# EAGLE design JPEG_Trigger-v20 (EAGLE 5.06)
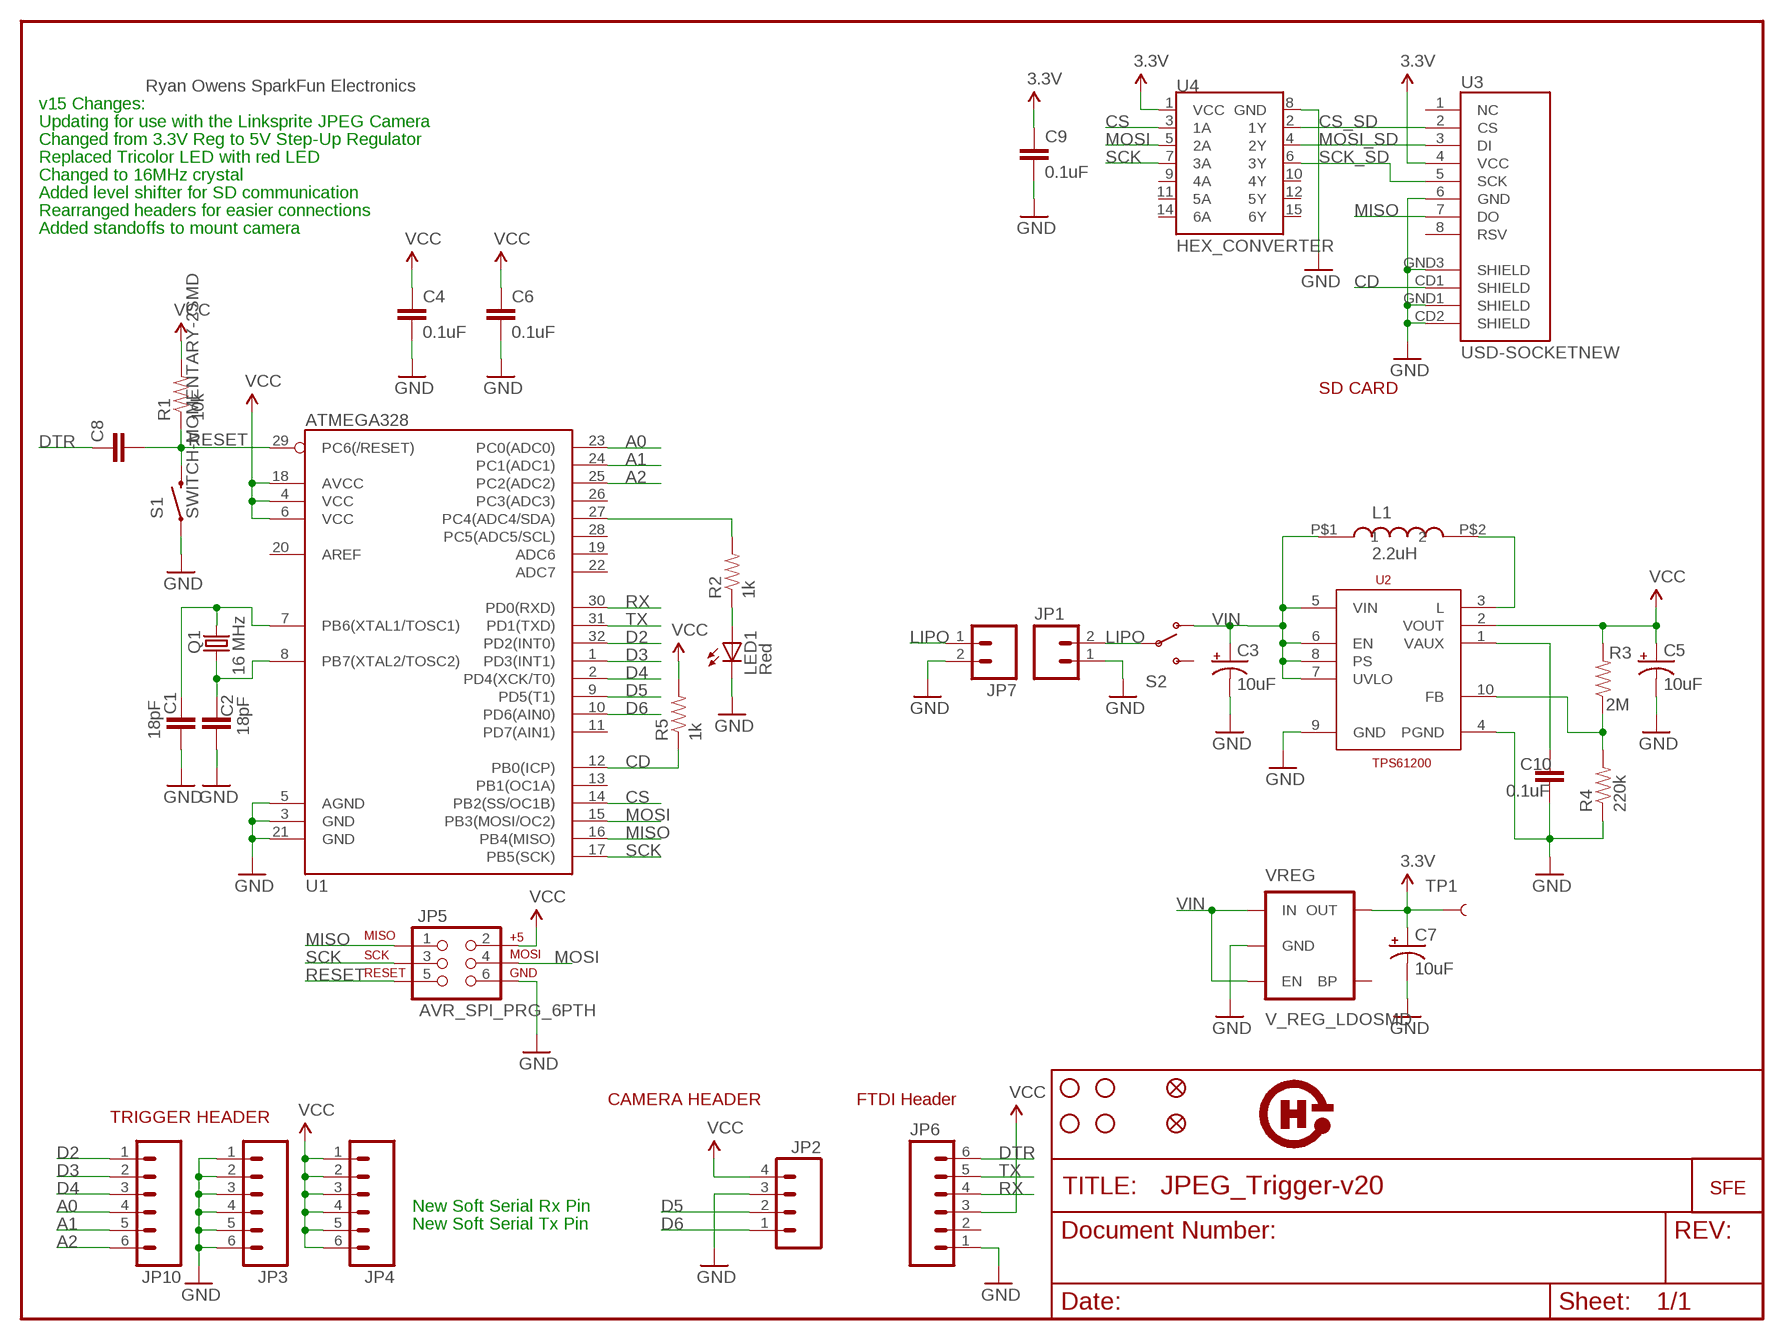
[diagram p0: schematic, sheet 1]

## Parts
C1  18pF  CAP0402-CAP  [0402-CAP]
C2  18pF  CAP0402-CAP  [0402-CAP]
C3  10uF  CAP_POL1206  [EIA3216]
C4  0.1uF  CAP0402-CAP  [0402-CAP]
C5  10uF  CAP_POL1206  [EIA3216]
C6  0.1uF  CAP0402-CAP  [0402-CAP]
C7  10uF  CAP_POL1206  [EIA3216]
C8  .1uF  CAP0402-CAP  [0402-CAP]
C9  0.1uF  CAP0402-CAP  [0402-CAP]
C10  0.1uF  CAP0402-CAP  [0402-CAP]
JP1  M02-JST-2MM-SMT  [JST-2-SMD]
JP2  M04PTH  [1X04]
JP3  M06SIP  [1X06]
JP4  M06SIP  [1X06]
JP5  AVR_SPI_PRG_6PTH  [2X3]
JP6  M06SIP  [1X06]
JP7  M02PTH  [1X02]
JP8  STAND-OFF  [STAND-OFF]
JP9  STAND-OFF  [STAND-OFF]
JP10  M06SIP  [1X06]
JP11  STAND-OFF  [STAND-OFF]
JP12  STAND-OFF  [STAND-OFF]
JP13  FIDUCIAL1X2  [FIDUCIAL-1X2]
JP14  FIDUCIAL1X2  [FIDUCIAL-1X2]
L1  2.2uH  VLF4012A  [VLF4012A]
LED1  Red  LED0603  [LED-0603]
Q1  16 MHz  CRYSTAL5X3  [CRYSTAL-SMD-5X3]
R1  10k  RESISTOR0402-RES  [0402-RES]
R2  1k  RESISTOR0402-RES  [0402-RES]
R3  2M  RESISTOR0402-RES  [0402-RES]
R4  220k  RESISTOR0402-RES  [0402-RES]
R5  1k  RESISTOR0402-RES  [0402-RES]
S1  SWITCH-MOMENTARY-2SMD  [TACTILE_SWITCH_SMD]
S2  SWITCH-SPSTSMD2  [SWITCH-SPDT-SMD]
TP1  TEST-POINT3X5  [PAD.03X.05]
U1  ATMEGA328  ATMEGA168  [TQFP32-08]
U2  TPS61200  [DRC-S-PVSON-N10]
U3  USD-SOCKETNEW  [MICRO-SD-SOCKET-PP]
U4  HEX_CONVERTER  [SO016]
U$1  LOGO-SFENEW  [SFE-NEW-WEBLOGO]
U$2  OSHW-LOGO  [OSHW-LOGO]
VREG  V_REG_LDOSMD  [SOT23-5]

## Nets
3.3V: C7.A(+) C9.1 TP1.P$1 U3.4(VCC) U4.1(VCC) VREG.5(OUT)
A0: JP10.4 U1.23(PC0(ADC0))
A1: JP10.5 U1.24(PC1(ADC1))
A2: JP10.6 U1.25(PC2(ADC2))
CD: R5.1 U1.12(PB0(ICP)) U3.CD1(SHIELD)
CS: U1.14(PB2(SS/OC1B)) U4.3(1A)
CS_SD: U3.2(CS) U4.2(1Y)
D2: JP10.1 U1.32(PD2(INT0))
D3: JP10.2 U1.1(PD3(INT1))
D4: JP10.3 U1.2(PD4(XCK/T0))
D5: JP2.2 U1.9(PD5(T1))
D6: JP2.1 U1.10(PD6(AIN0))
DTR: C8.1 JP6.6
GND: C1.2 C2.2 C3.C(-) C4.2 C5.C(-) C6.2 C7.C(-) C9.2 C10.2 JP1.1 JP2.3 JP3.1 JP3.2 JP3.3 JP3.4 JP3.5 JP3.6 JP5.6 JP6.1 JP7.2 LED1.C R4.1 S1.1 U1.3(GND) U1.5(AGND) U1.21(GND) U2.4(PGND) U2.9(GND) U3.6(GND) U3.CD2(SHIELD) U3.GND1(SHIELD) U3.GND3(SHIELD) U4.8(GND) VREG.2(GND)
LIPO: JP1.2 JP7.1 S2.2(P)
MISO: JP5.1 U1.16(PB4(MISO)) U3.7(DO)
MOSI: JP5.4 U1.15(PB3(MOSI/OC2)) U4.5(2A)
MOSI_SD: U3.3(DI) U4.4(2Y)
N$1: C1.1 Q1.3 U1.7(PB6(XTAL1/TOSC1))
N$2: C2.1 Q1.1 U1.8(PB7(XTAL2/TOSC2))
N$4: LED1.A R2.1
N$5: L1.P$2 U2.3(L)
N$6: C10.1 U2.1(VAUX)
N$7: R3.1 R4.2 U2.10(FB)
R: R2.2 U1.27(PC4(ADC4/SDA))
RESET: C8.2 JP5.5 R1.1 S1.3 U1.29(PC6(/RESET))
RX: JP6.4 U1.30(PD0(RXD))
SCK: JP5.3 U1.17(PB5(SCK)) U4.7(3A)
SCK_SD: U3.5(SCK) U4.6(3Y)
TX: JP6.5 U1.31(PD1(TXD))
VCC: C4.1 C5.A(+) C6.1 JP2.4 JP4.1 JP4.2 JP4.3 JP4.4 JP4.5 JP4.6 JP5.2 JP6.3 R1.2 R3.2 R5.2 U1.4(VCC) U1.6(VCC) U1.18(AVCC) U2.2(VOUT)
VIN: C3.A(+) L1.P$1 S2.1(O) U2.5(VIN) U2.6(EN) U2.7(UVLO) U2.8(PS) VREG.1(IN) VREG.3(EN)
Unconnected: JP6.2 S2.3(S) U1.11(PD7(AIN1)) U1.13(PB1(OC1A)) U1.19(ADC6) U1.20(AREF) U1.22(ADC7) U1.26(PC3(ADC3)) U1.28(PC5(ADC5/SCL)) U3.1(NC) U3.8(RSV) U4.9(4A) U4.10(4Y) U4.11(5A) U4.12(5Y) U4.14(6A) U4.15(6Y) VREG.4(BP)

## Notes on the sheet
- Ryan Owens SparkFun Electronics
- v15 Changes:
- Updating for use with the Linksprite JPEG Camera
- Changed from 3.3V Reg to 5V Step-Up Regulator
- Replaced Tricolor LED with red LED
- Changed to 16MHz crystal
- Added level shifter for SD communication
- Rearranged headers for easier connections
- Added standoffs to mount camera
- SD CARD
- CAMERA HEADER | FTDI Header
- TRIGGER HEADER
- New Soft Serial Rx Pin
- New Soft Serial Tx Pin

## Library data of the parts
C1 C2 C4 C6 C8-C10 = SparkFun:CAP: Capacitor
C3 C5 C7 = SparkFun:CAP_POL: Capacitor Polarized
JP1 JP7 = SparkFun:M02: Header 2
JP2 = SparkFun:M04: Header 4 Standard 4-pin 0.1" header. Use with straight break away headers (SKU : PRT-00116), right angle break away headers (PRT-00553), swiss pins (PRT-00743), machine pins (PRT-00117), and female headers (PRT-00115). Molex polarized connector foot print use with SKU : PRT-08231 with associated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
JP3 JP4 JP6 JP10 = SparkFun:M06: Header 6 Standard 6-pin 0.1" header. Use with straight break away headers (SKU : PRT-00116), right angle break away headers (PRT-00553), swiss pins (PRT-00743), machine pins (PRT-00117), and female headers (PRT-00115). Molex polarized connector foot print use with SKU : PRT-08094 with associated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
JP5 = SparkFun:AVR_SPI_PRG_6: AVR ISP 6 Pin This is the reduced ISP connector for AVR programming. Common on Arduino. This footprint will take up less PCB space and can be used with a 10-pin to 6-pin adapter such as SKU: BOB-08508
JP8 JP9 JP11 JP12 = SparkFun:STAND-OFF: Stand Off
JP13 JP14 = SparkFun:FIDUCIAL: Fiducial Alignment Points
L1 = PEBBLE:VLF4012A
LED1 = SparkFun:LED: LEDs
Q1 = SparkFun:CRYSTAL: Crystals
R1-R5 = SparkFun:RESISTOR: Resistor
S1 = SparkFun:SWITCH-MOMENTARY-2
S2 = SparkFun:SWITCH-SPST: SPST Switch Simple slide switch. Spark Fun Electronics SKU : COM-00102
TP1 = SparkFun:TEST-POINT
U1 = SparkFun:ATMEGA168
U2 = texas:TPS61200
U3 = SparkFun:USD-SOCKET: microSD Socket Push-push type uSD socket. Schematic element and footprint production proven. Spark Fun Electronics SKU : PRT-00127. tDoc lines correctly indicate media card edge positions when inserting (unlocked, locked, depressed).
U4 = SparkFun:HEX_CONVERTER
U$1 = SparkFun:LOGO-SFE: Spark Fun Electronics PCB Logo
U$2 = OSHW:OSHW-LOGO
VREG = SparkFun:V_REG_LDO: Voltage Regulator LDO Standard 150mA LDO voltage regulator in SOT-23 layout. Micrel part MIC5205. BP (by-pass) pin is used to lower output noise with 470pF cap.

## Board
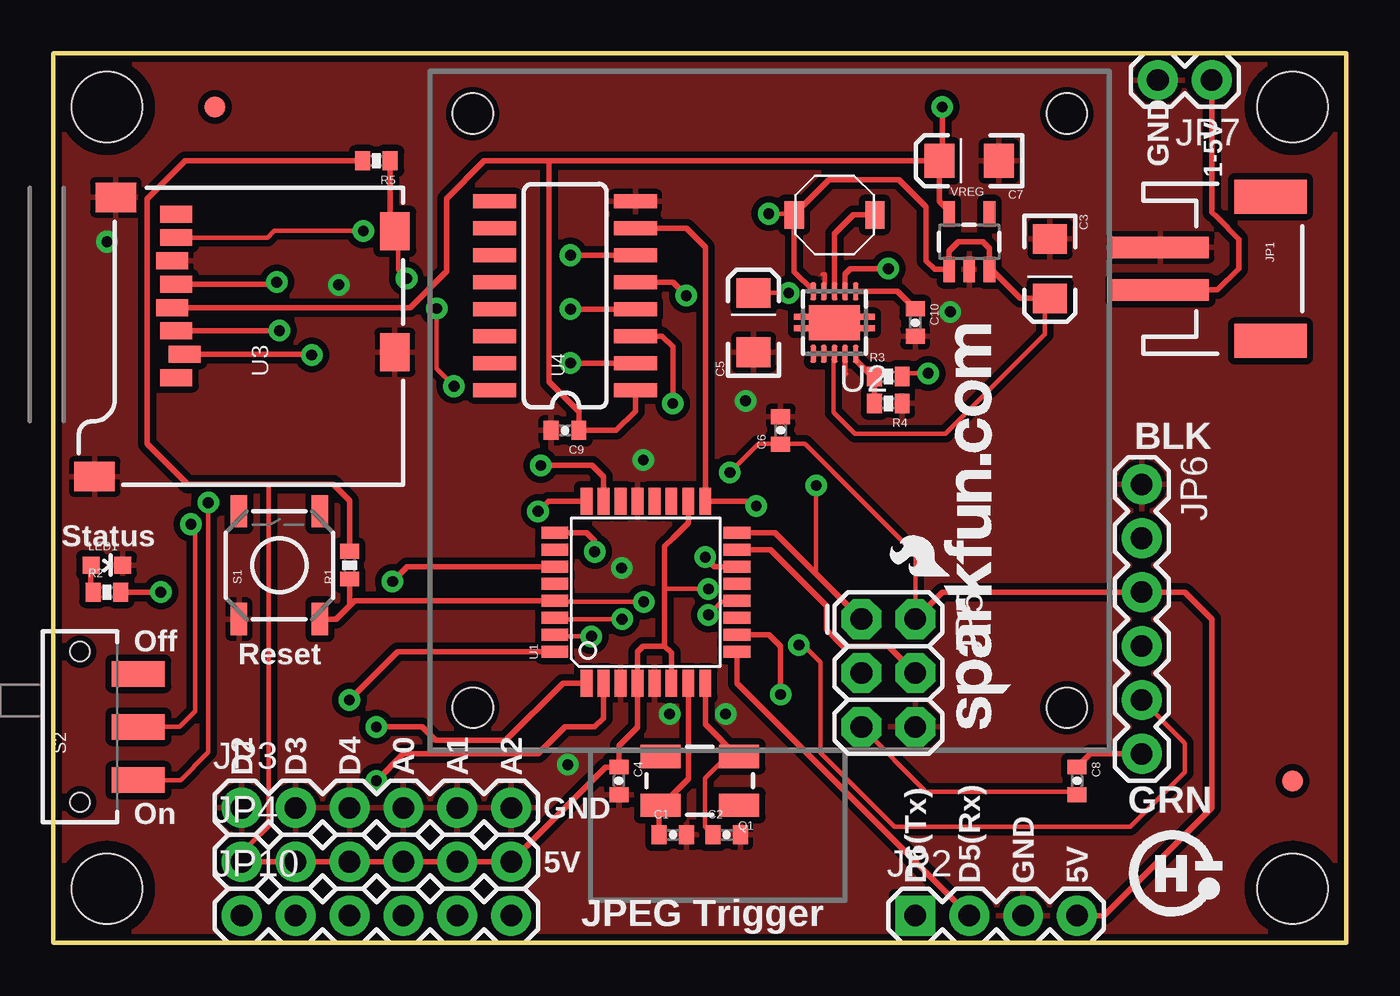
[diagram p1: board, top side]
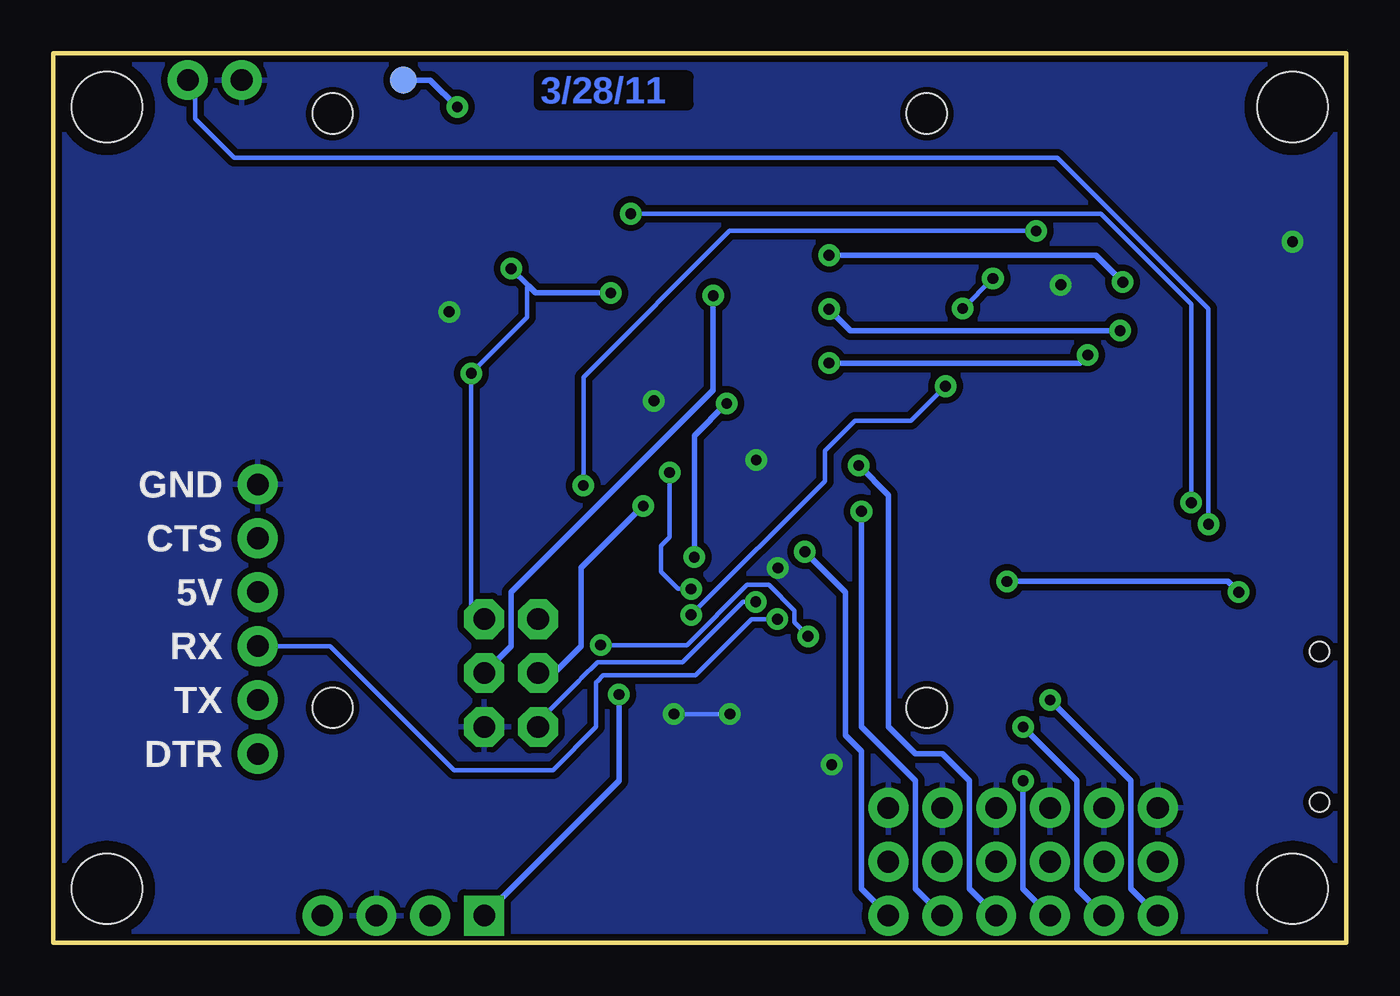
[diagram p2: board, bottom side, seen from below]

Size 60.96 x 41.91 mm. Coordinates in mm from the lower left corner, seen from the top.
Outline: 0,0 60.96,0 60.96,41.91 0,41.91 0,0
Copper layers (1*16): Top 0.035mm / dielectric 1.5mm / Bottom 0.035mm
Design rules "SparkFun": minimum track width 8mil, minimum drill 20mil, track to track 8mil, track to pad 8mil, pad to pad 8mil, via to via 8mil, smd to smd 8mil, copper to edge 9mil, drill to drill 8mil, minimum pad ring 12mil, minimum via ring 10mil, stop-mask expansion 4mil, vias tented up to drill 20mil, thermal gap 10mil
Holes 1.89 mm at 19.78,39.06 47.78,39.06 47.78,11.06 19.78,11.06

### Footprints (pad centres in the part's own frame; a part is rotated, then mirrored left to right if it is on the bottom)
0402-CAP = smd 0.7 x 0.9: 1 -0.65,0; 2 0.65,0
EIA3216 = smd 1.4 x 1.6: A 1.4,0; C -1.4,0
JST-2-SMD = smd 1 x 4.6: 1 -1,-3.7; 2 1,-3.7 | smd 1.6 x 3.4: NC1 -3.4,1.5; NC2 3.4,1.5
1X04 = drill 1.016 pad 1.88 square: 1 0,0 | drill 1.016 pad 1.88 round: 2 2.54,0; 3 5.08,0; 4 7.62,0
1X06 = drill 1.016 pad 1.88 round: 1 0,0; 2 2.54,0; 3 5.08,0; 4 7.62,0; 5 10.16,0; 6 12.7,0
2X3 = drill 1.016 pad 1.88 octagon: 1 0,0; 2 0,2.54; 3 2.54,0; 4 2.54,2.54; 5 5.08,0; 6 5.08,2.54
1X02 = drill 1.016 pad 1.88 round: 1 0,0; 2 2.54,0
STAND-OFF = hole 3.302: 0,0
FIDUCIAL-1X2 = smd 1 x 1: 1 0,0
VLF4012A = smd 0.9 x 1.3: P$1 -1.9,0; P$2 1.9,0
LED-0603 = smd 0.8 x 0.8: A 0,-0.75; C 0,0.75
CRYSTAL-SMD-5X3 = smd 1.9 x 1.1: 1 -1.85,-1.15; 2 1.85,-1.15; 3 1.85,1.15; 4 -1.85,1.15
0402-RES = smd 0.7 x 0.9: 1 -0.65,0; 2 0.65,0
TACTILE_SWITCH_SMD = smd 1.524 x 0.762: 1 -2.54,1.905; 2 2.54,1.905; 3 -2.54,-1.905; 4 2.54,-1.905
SWITCH-SPDT-SMD = smd 1.2 x 2.5: 1 -2.5,-2.75; 2 0,-2.75; 3 2.5,-2.75 | hole 0.9: -3.55,0; 3.55,0
PAD.03X.05 = smd 1.27 x 1.27: P$1 0,0
TQFP32-08 = smd 1.27 x 0.559: 1 -4.293,2.8; 2 -4.293,2; 3 -4.293,1.2; 4 -4.293,0.4; 5 -4.293,-0.4; 6 -4.293,-1.2; 7 -4.293,-2; 8 -4.293,-2.8; 17 4.293,-2.8; 18 4.293,-2; 19 4.293,-1.2; 20 4.293,-0.4; 21 4.293,0.4; 22 4.293,1.2; 23 4.293,2; 24 4.293,2.8 | smd 0.559 x 1.27: 9 -2.8,-4.293; 10 -2,-4.293; 11 -1.2,-4.293; 12 -0.4,-4.293; 13 0.4,-4.293; 14 1.2,-4.293; 15 2,-4.293; 16 2.8,-4.293; 25 2.8,4.293; 26 2,4.293; 27 1.2,4.293; 28 0.4,4.293; 29 -0.4,4.293; 30 -1.2,4.293; 31 -2,4.293; 32 -2.8,4.293
DRC-S-PVSON-N10 = smd 0.28 x 0.85: 1 -1,-1.475; 2 -0.5,-1.475; 3 0,-1.475; 4 0.5,-1.475; 5 1,-1.475; 6 1,1.475; 7 0.5,1.475; 8 0,1.475; 9 -0.5,1.475; 10 -1,1.475 | smd 2.4 x 1.65: TH 0,0 | smd 3.8 x 0.28: TH@1 0,0.275; TH@2 0,-0.275
MICRO-SD-SOCKET-PP = smd 0.8 x 1.5: 1 -8.94,10.7; 2 -7.84,10.3; 3 -6.74,10.7; 4 -5.64,10.9; 5 -4.54,10.7; 6 -3.44,10.9; 7 -2.34,10.7; 8 -1.24,10.7 | smd 1.8 x 1.4: CD1 -2.05,0.4; CD2 -7.75,0.4 | smd 1.4 x 1.9: GND1 -13.6,14.55; GND3 -0.45,13.55
SO016 = smd 0.66 x 2.032: 1 -4.445,-3.315; 2 -3.175,-3.315; 3 -1.905,-3.315; 4 -0.635,-3.315; 5 0.635,-3.315; 6 1.905,-3.315; 7 3.175,-3.315; 8 4.445,-3.315; 9 4.445,3.315; 10 3.175,3.315; 11 1.905,3.315; 12 0.635,3.315; 13 -0.635,3.315; 14 -1.905,3.315; 15 -3.175,3.315; 16 -4.445,3.315
SOT23-5 = smd 0.55 x 1.2: 1 -0.95,-1.3; 2 0,-1.3; 3 0.95,-1.3; 4 0.95,1.3; 5 -0.95,1.3

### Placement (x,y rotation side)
C1  29.21,5.08 0 top
C2  31.75,5.08 0 top
C3  46.99,31.75 270 top
C4  26.67,7.62 270 top
C5  33.02,29.21 90 top
C6  34.29,24.13 90 top
C7  43.18,36.83 180 top
C8  48.26,7.62 270 top
C9  24.13,24.13 180 top
C10  40.64,29.21 270 top
JP1  55.88,31.75 270 top
JP2  40.64,1.27 0 top
JP3  8.89,6.35 0 top
JP4  8.89,3.81 0 top
JP5  38.1,15.24 270 top
JP6  51.31,21.59 270 top
JP7  54.61,40.64 180 top
JP8  2.54,39.37 0 top
JP9  58.42,39.37 0 top
JP10  8.89,1.27 0 top
JP11  2.54,2.54 0 top
JP12  58.42,2.54 0 top
JP13  7.62,39.37 0 top
JP14  58.42,7.62 0 top
L1  36.83,34.29 0 top
LED1  2.54,17.78 270 top
Q1  30.48,7.62 180 top
R1  13.97,17.78 90 top
R2  2.54,16.51 0 top
R3  39.37,26.67 0 top
R4  39.37,25.4 180 top
R5  15.24,36.83 180 top
S1  10.67,17.78 90 top
S2  1.27,10.16 90 top
TP1  44.45,40.64 0 bottom
U1  27.94,16.51 90 top
U2  36.83,29.21 180 top
U3  16.51,35.56 90 top
U4  24.13,30.48 90 top
U$1  45.14,10.08 90 top
U$2  52.7,3.3 0 top
VREG  43.18,33.02 0 top

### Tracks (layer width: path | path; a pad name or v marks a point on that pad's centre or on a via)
3.3V  (via drill 0.51)
  Top 0.254: VREG.5 42.23,34.36 42.29,34.42 41.78,34.93 C7.A | U4.1 27.45,25.03 26.54,24.13 C9.1 24.78,25 23.37,26.42 23.37,36.83 | U3.4 16.84,29.92 18.54,31.62 18.54,35.05 20.32,36.83 23.37,36.83 | 23.37,36.83 C7.A | v41.91,39.37 41.91,36.96 C7.A
  Bottom 0.254: TP1.P$1 43.18,40.64 v41.91,39.37
A0  (via drill 0.51)
  Top 0.254: U1.23 25.94,21.94 25.4,22.48 v22.99,22.48
  Bottom 0.254: JP10.4 17.78,2.54 17.78,7.62 19.05,8.89 20.32,8.89 21.59,10.16 21.59,21.08 v22.99,22.48
A1  (via drill 0.51)
  Top 0.254: U1.24 23.34,20.8 v22.86,20.32
  Bottom 0.254: JP10.5 20.32,2.54 20.32,7.62 22.86,10.16 v22.86,20.32
A2  (via drill 0.51)
  Top 0.254: U1.25 25.14,19.31 25.53,18.92 v25.53,18.41
  Bottom 0.254: JP10.6 22.86,2.54 22.86,7.62 22.86,9.02 23.62,9.78 23.62,16.51 v25.53,18.41
CD  (via drill 0.51)
  Top 0.203: v30.89,15.44 31.5,16.05 31.7,16.05 U1.12 | v18.9,26.21 18.09,27.03 v18.09,29.87 | v16.66,31.29 16.26,31.7 16.26,32.72 U3.CD1
  Top 0.254: R5.1 15.88,36.81 15.88,36.7 15.88,33.74 U3.CD1
  Bottom 0.203: v30.89,15.44 24.59,21.74 24.59,23.16 23.16,24.59 20.52,24.59 v18.9,26.21 | v18.09,29.87 v16.66,31.29
CS  (via drill 0.51)
  Top 0.254: U1.14 31.18,17.71 v30.73,18.16 | v29.21,25.4 29.21,28.07 28.7,28.57 U4.3
  Bottom 0.254: v30.73,18.16 30.73,23.88 v29.21,25.4
CS_SD  (via drill 0.51)
  Top 0.254: U3.2 12.16,27.72 v12.19,27.69 | v24.38,27.3 U4.2
  Bottom 0.254: v12.19,27.69 12.57,27.3 v24.38,27.3
D2  (via drill 0.51)
  Top 0.254: U1.32 16.25,13.71 v13.97,11.43
  Bottom 0.254: JP10.1 10.16,2.54 10.16,7.62 v13.97,11.43
D3  (via drill 0.51)
  Top 0.254: v15.24,10.16 17.4,10.16 18.03,9.53 21.34,9.53 24,12.19 24.03,12.22 U1.1
  Bottom 0.254: JP10.2 12.7,2.54 12.7,7.24 12.7,7.62 v15.24,10.16
D4  (via drill 0.51)
  Top 0.254: U1.2 25.94,10.57 25.53,10.16 24.13,10.16 22.86,8.89 16.51,8.89 v15.24,7.62
  Bottom 0.254: JP10.3 15.24,2.54 v15.24,7.62
D5
  Top 0.254: U1.9 32.23,12.22 34.29,10.16 JP2.2
D6  (via drill 0.51)
  Top 0.254: U1.10 33.75,14.51 34.29,13.97 v34.29,11.68
  Bottom 0.254: v34.29,11.68 34.29,7.62 JP2.1
DTR
  Top 0.254: C8.1 48.88,8.89 JP6.6
GND  (via drill 0.51)
  Top 0.203: U2.4 36.37,31.09 36.37,31.5 36.27,31.5
  Top 0.254: U2.9 37.33,26.8 37.34,26.8
  Bottom 0.203: v29.06,10.77 v31.7,10.77
  other vias: 24.26,8.38 27.81,22.73 26.8,17.65 32.64,25.53 42.29,29.72 13.46,30.99 2.54,33.02
  pour Top (isolate 0.305): 0,0 0,41.91 60.96,41.91 60.96,0
  pour Bottom (isolate 0.305): 0,0 0,41.91 60.96,41.91 60.96,0
LIPO  (via drill 0.51)
  Top 0.203: v6.5,19.71 6.71,19.51 6.71,10.97 6.71,10.9 6.6,10.79 5.97,10.16 S2.2
  Top 0.254: JP1.2 54.88,30.75 55.88,31.75 55.88,33.15 54.86,34.16 54.61,34.42 JP7.1
  Bottom 0.203: v6.5,19.71 6.5,29.87 13.61,36.98 52.43,36.98 54.25,38.81 54.25,39.83 JP7.1
MISO  (via drill 0.51)
  Top 0.203: v35.97,21.54 35.97,17.48 35.92,17.42 | U3.7 10.11,33.22 10.41,33.53 14.48,33.53 v14.63,33.53
  Top 0.254: U1.16 34.03,19.31 35.92,17.42 JP5.1
  Bottom 0.203: v14.63,33.53 23.37,33.53 29.08,33.53 35.94,26.67 35.97,26.64 35.97,26.62 v35.97,21.54
MOSI  (via drill 0.51)
  Top 0.254: U1.15 33.81,18.51 36.45,15.88 36.45,14.73 37.21,13.97 39.37,13.97 JP5.4 | U4.5 29.21,31.11 v29.84,30.48
  Bottom 0.254: v29.84,30.48 29.84,26.04 35.56,20.32 39.37,16.51 39.37,14.48 39.37,13.97 JP5.4
MOSI_SD  (via drill 0.51)
  Top 0.254: U3.3 v10.66,28.82 v10.67,28.83 | v24.38,29.84 U4.4
  Bottom 0.254: v10.67,28.83 23.37,28.83 v24.38,29.84
N$1
  Top 0.254: U1.7 29.94,7.71 28.7,6.48 28.7,6.47 Q1.3 28.63,6.28 28.57,6.22 28.56,6.21 C1.1
N$2
  Top 0.203: 32.26,8.76 31.75,8.76 30.73,7.75 30.73,5.46 31.11,5.08 C2.1
  Top 0.254: Q1.1 32.27,8.77 32.26,8.76 30.74,10.28 U1.8
N$4
  Top 0.254: LED1.A 1.78,17.77 1.78,17.65 1.78,16.62 R2.1
N$5
  Top 0.254: U2.3 36.83,33.4 37.72,34.29 L1.P$2
N$6
  Top 0.254: C10.1 40.64,29.84 39.8,30.68 U2.1
N$7
  Top 0.254: U2.10 37.83,27.45 38.61,26.67 R3.1 38.72,26.56 38.73,26.54 38.72,26.53 R4.2
R  (via drill 0.51)
  Top 0.254: U1.27 16.69,17.71 v16,17.02 | R2.2 v5.08,16.51
  Bottom 0.254: v16,17.02 5.59,17.02 v5.08,16.51
RESET  (via drill 0.51)
  Top 0.203: C8.2 47.95,7.11 41.15,7.11 JP5.5 | v27.84,16.05 24.18,16.05 U1.29
  Top 0.254: S1.3 13.34,15.24 13.97,15.88 | R1.1 13.97,17.02 13.97,15.88 | U1.29 14.21,16.11 13.97,15.88
  Bottom 0.203: v27.84,16.05 28.45,16.05 31.29,13.21 34.95,13.21 35.31,13.21 36.07,12.45 36.17,12.34 38.1,10.41 JP5.5
RX  (via drill 0.51)
  Top 0.203: v26.82,15.24 24.18,15.24 U1.30
  Bottom 0.203: v26.82,15.24 28.04,15.24 30.68,12.6 34.95,12.6 35.03,12.6 35.31,12.32 35.36,12.27 35.36,12.19 35.36,10.16 37.39,8.13 42.06,8.13 47.55,13.61 47.9,13.97 JP6.4
SCK  (via drill 0.51)
  Top 0.254: U4.7 29.84,33.66 30.48,33.02 30.74,32.76 U1.17 32.92,20.8 v33.15,20.57
  Bottom 0.254: v33.15,20.57 36.07,17.65 36.07,15.75 36.07,13.97 37.34,12.7 JP5.3
SCK_SD  (via drill 0.51)
  Top 0.254: U3.5 10.45,31.02 v10.54,31.11 | v24.38,32.38 U4.6
  Bottom 0.254: v10.54,31.11 11.81,32.38 v24.38,32.38
TX  (via drill 0.51)
  Top 0.203: v25.38,14.43 24.18,14.43 U1.31 | v35.15,14.02 35.36,14.02 36.17,13.21 36.17,8.94 39.65,5.46 50.67,5.46 50.77,5.46 50.8,5.49 53.24,7.92 53.34,8.03 53.34,8.13 53.34,9.4 JP6.5
  Bottom 0.203: v35.15,14.02 31.09,14.02 28.25,16.87 27.23,16.87 26.01,15.65 26.01,15.44 26.01,15.09 25.4,14.48 25.38,14.45 v25.38,14.43
VCC  (via drill 0.51)
  Top 0.203: v41.25,26.82 40.23,26.82 R3.2 | JP5.2 40.64,16.05 40.64,18.29 35.76,23.16 35.43,23.5 34.42,23.5 34.3,23.5 C6.1 34.29,23.5 33.25,23.5 v31.9,22.15 | v30.89,16.66 28.85,16.66 28.83,16.64 | JP4.1 9.35,4.67 10.16,5.49 10.16,21.54 10.16,21.59 | v34.67,30.61 34.54,30.61 C5.A
  Top 0.254: JP4.1 JP4.2 JP4.3 JP4.4 JP4.5 JP4.6 26.04,8.26 26.67,8.26 | U1.6 29.14,13.66 28.83,13.97 | 28.83,13.97 27.94,13.97 27.81,13.97 27.54,13.7 U1.4 27.54,10.14 26.67,9.27 26.67,8.26 | 28.83,13.97 28.83,16.64 28.83,16.89 28.83,18.67 29.21,19.05 29.94,19.78 U1.18 | v34.67,30.61 | U2.2 37.33,31.49 37.59,31.75 v39.37,31.75 | JP2.4 49.53,1.27 54.61,6.35 54.61,15.24 53.34,16.51 JP6.3 51.18,16.51 41.91,16.51 JP5.2 | 26.67,8.26 C4.1 26.67,8.26 | R5.2 6.22,36.83 4.45,35.05 4.45,23.5 6.35,21.59 10.16,21.59 13.21,21.59 13.97,20.83 13.97,18.54 R1.2
  Bottom 0.203: 38.56,30.94 38.61,30.89 38.61,29.46 v41.25,26.82 41.25,26.42 41.25,15.85 JP5.2 | v31.9,22.15 31.9,19.1 32.31,18.69 32.31,17.48 31.5,16.66 v30.89,16.66
  Bottom 0.254: v34.67,30.61 38.23,30.61 38.56,30.94 v39.37,31.75
VIN  (via drill 0.51)
  Top 0.203: U2.8 36.78,27.43 36.78,24.99 37.8,23.98 42.06,23.98 46.74,28.65 46.74,29.67 C3.A | v7.32,20.73 7.32,9.14 7.32,8.97 7.24,8.89 6.01,7.66 S2.1 | v33.73,34.34 34.54,34.34 L1.P$1
  Top 0.254: U2.5 35.83,30.72 35.81,30.73 34.93,31.62 L1.P$1 36.58,35.94 39.88,35.94 41.15,34.67 41.15,32.13 41.56,31.72 VREG.1 42.23,32.58 42.67,33.02 43.81,33.02 44.13,32.7 VREG.3 44.17,31.72 44.2,31.75 45.6,30.35 C3.A | U2.6 36.27,27.73 36.32,27.69 36.33,27.69 U2.7 36.78,27.73 36.83,27.69 U2.8
  Bottom 0.203: v7.32,20.73 7.32,30.07 11.58,34.34 v33.73,34.34

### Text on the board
Bottom: 3/28/11
tPlace: GND | 1-5V | BLK | Status | Off | Reset | D2 | D3 | D4 | A0 | A1 | A2 | GRN | On | GND | 5V | D6(Tx) | D5(Rx) | GND | 5V | JPEG Trigger
bPlace: GND | CTS | 5V | RX | TX | DTR
Reference: 3.3V TP | SD CARD
tDocu: Camera Outline if place | on top of board | Bottom of Viewport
